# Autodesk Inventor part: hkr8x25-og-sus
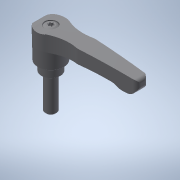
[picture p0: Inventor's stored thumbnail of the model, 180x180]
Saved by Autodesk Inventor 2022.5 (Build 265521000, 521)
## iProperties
Created: 2017-09
Part Number: hkr8x25-og-sus
Material: 一般
Document SubType Name: Modeling
Designer: imaocorp
Density: 1 g/cm^3
Appearance: 既定
Author: imaocorp
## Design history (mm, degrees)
node "hkr8x25-og-sus.x_t1"
node "hkr8x25-og-sus"
node "Base1"
